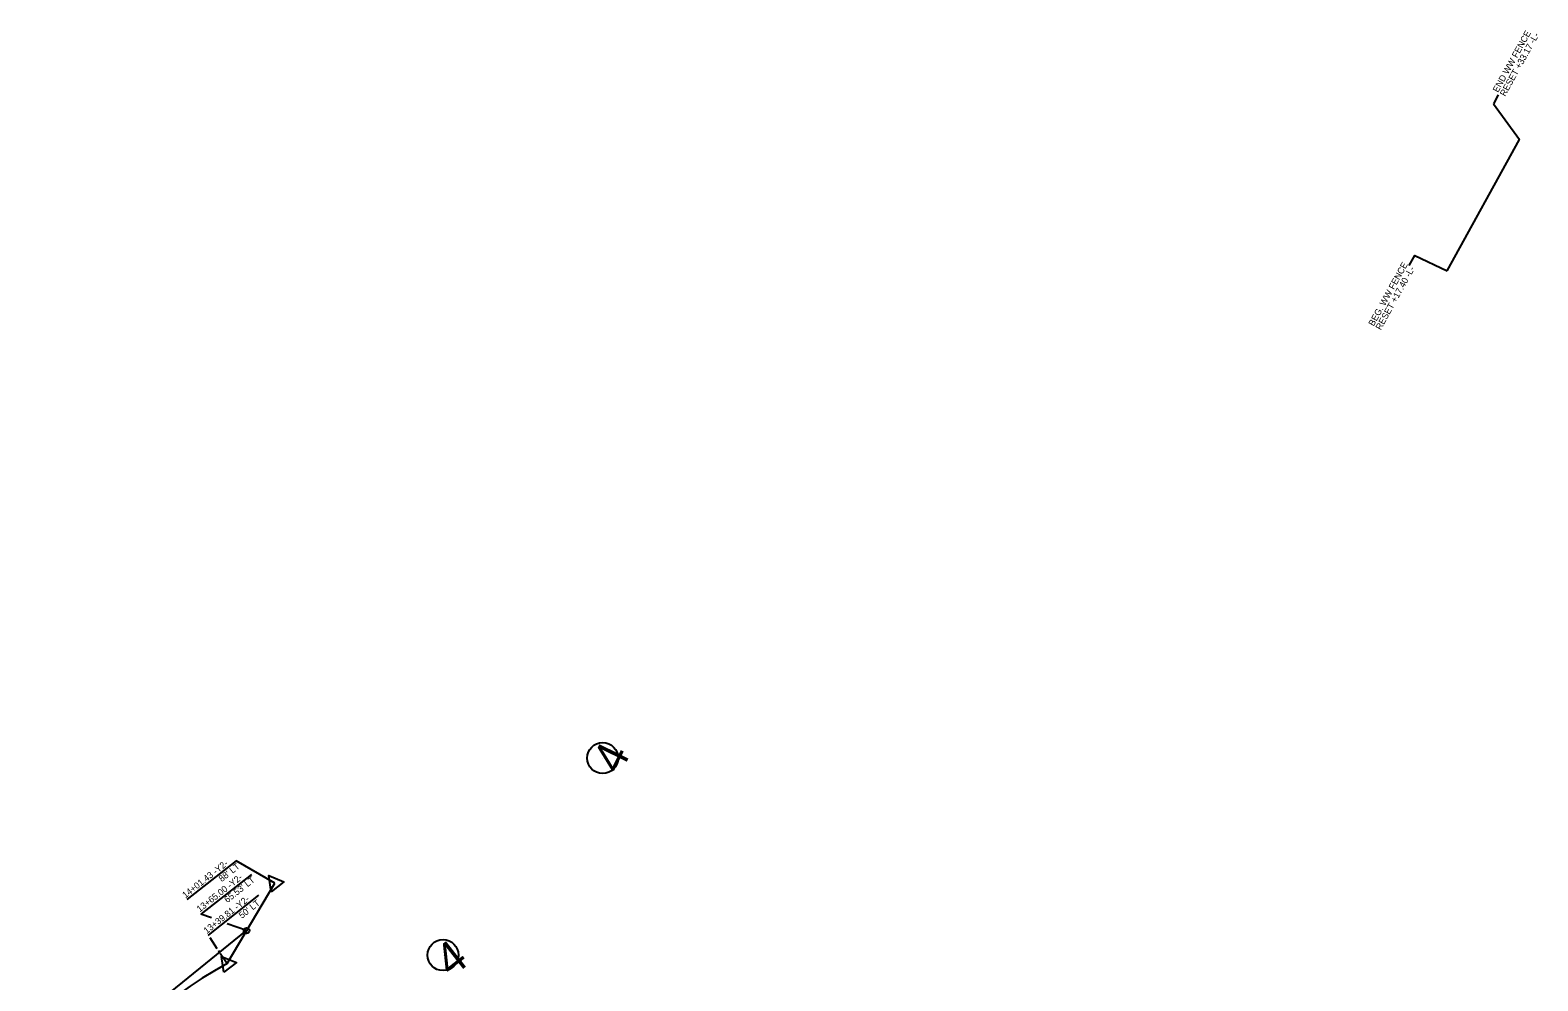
# Model space of a CAD drawing. Extents: x 2175623 to 2194100, y 76458 to 87202.
# Drawn here: x 2175913 to 2177079, y 77699 to 78434 of the extents above; entities that cross this region are included whole.
import ezdxf

# ---------------------------------------------------------------- set-up
doc = ezdxf.new("R2010")
doc.units = 0
for name, color, linetype in [('Exist Plan Preparation Drainage Flow Arrows', 7, 'Continuous'), ('Exist Property Iron Pin CELL', 7, 'Continuous'), ('Prop Drainage Structure Box Number Symbol CELL', 7, 'Continuous'), ('Prop Drainage Structure Pipe RCP 36in Class IV', 7, 'Continuous'), ('Prop Drainage Structure Pipe Removal Label', 7, 'Continuous'), ('Prop Erosion Rip Rap Pad at Outlet Label', 7, 'Continuous'), ('Prop Plan Preparation Crest Label', 7, 'Continuous'), ('Prop Plan Preparation Sag', 7, 'Continuous'), ('Prop Plan Preparation Sag Label', 7, 'Continuous'), ('Scratch_Level_3', 7, 'Continuous')]:
    doc.layers.add(name, color=color, linetype=linetype)

msp = doc.modelspace()

# ---------------------------------------------------------------- linework, layer by layer
at = {"layer": 'Exist Plan Preparation Drainage Flow Arrows'}
msp.add_line((2176065.7, 77712.6), (2176102.5, 77774.9), dxfattribs=at)
msp.add_arc((2176198.4, 77460.4), 285, 117.7626, 187.9763, dxfattribs=at)
at = {"layer": 'Exist Property Iron Pin CELL'}
for radius in [2.2, 0.0707]:
    msp.add_circle((2176080.7, 77738.1), radius, dxfattribs=at)
at = {"layer": 'Prop Drainage Structure Box Number Symbol CELL'}
for p, q in [((2176355.9, 77871.5), (2176355.9, 77871.5)), ((2176232.5, 77719.2), (2176232.5, 77719.2))]:
    msp.add_line(p, q, dxfattribs=at)
for centre in [(2176355.9, 77871.5), (2176232.5, 77719.2)]:
    msp.add_circle(centre, 12, dxfattribs=at)
at = {"layer": 'Prop Drainage Structure Pipe RCP 36in Class IV'}
for p, q in [((2176084.4, 77781.6), (2176045.3, 77750.8)), ((2176053.5, 77747.9), (2176045.3, 77750.8)), ((2176080.7, 77738.1), (2176065.7, 77743.5))]:
    msp.add_line(p, q, dxfattribs=at)
at = {"layer": 'Prop Drainage Structure Pipe Removal Label'}
msp.add_line((2177048.1, 78384), (2177044.3, 78377.1), dxfattribs=at)
for points in [[(2177044.3, 78377.1), (2177064.4, 78349.4)], [(2176979.3, 78252.2), (2176983.5, 78259.9), (2177008.5, 78248)]]:
    msp.add_lwpolyline(points, dxfattribs=at)
at = {"layer": 'Prop Plan Preparation Crest Label'}
for p, q in [((2176102.5, 77774.9), (2176102.5, 77774.9)), ((2176065.7, 77712.6), (2176065.7, 77712.6))]:
    msp.add_line(p, q, dxfattribs=at)
for points in [[(2176099.8, 77768.2), (2176098, 77780.6), (2176109.6, 77775.9)], [(2176063, 77705.9), (2176061.2, 77718.2), (2176072.8, 77713.6)]]:
    msp.add_lwpolyline(points, close=True, dxfattribs=at)
at = {"layer": 'Prop Plan Preparation Sag'}
for p, q in [((2176072.7, 77792.1), (2176034.4, 77762.1)), ((2176102.5, 77774.9), (2176072.7, 77792.1)), ((2176090, 77765.4), (2176050.9, 77734.7)), ((2176050.9, 77734.7), (2176051.2, 77734.3)), ((2176052.2, 77732.8), (2176057.8, 77724.4)), ((2176058.9, 77722.7), (2176059.6, 77721.6)), ((2176060.2, 77720.7), (2176065.7, 77712.6))]:
    msp.add_line(p, q, dxfattribs=at)
at = {"layer": 'Prop Plan Preparation Sag Label'}
msp.add_line((2176022, 77690.6), (2176080.7, 77738.1), dxfattribs=at)
at = {"layer": 'Scratch_Level_3'}
msp.add_line((2177008.5, 78248), (2177064.4, 78349.4), dxfattribs=at)

# ---------------------------------------------------------------- texts
at = {"layer": 'Prop Drainage Structure Pipe RCP 36in Class IV'}
for s, p in [('13+65.00 -Y2- ', (2176044.5, 77752.1)), ("65.53' LT", (2176065.8, 77759.3))]:
    msp.add_text(s, height=5, rotation=38.0951, dxfattribs=at).set_placement(p)
at = {"layer": 'Prop Drainage Structure Pipe Removal Label'}
for s, p in [('END WW FENCE', (2177047.9, 78385.4)), ('RESET +33.17 -L-', (2177053.4, 78382.4)), ('BEG. WW FENCE', (2176951.8, 78204.8)), ('RESET +17.40 -L-', (2176957.3, 78201.8))]:
    msp.add_text(s, height=5, rotation=61.0733, dxfattribs=at).set_placement(p)
at = {"layer": 'Prop Erosion Rip Rap Pad at Outlet Label'}
for rotation, p in [(63.5673, (2176369.4, 77858.2)), (38.0951, (2176238.9, 77701.4))]:
    msp.add_text('4', height=25, rotation=rotation, dxfattribs=at).set_placement(p)
at = {"layer": 'Prop Plan Preparation Sag'}
for s, p in [('14+01.43 -Y2- ', (2176033.4, 77762.9)), ("88' LT", (2176061.5, 77775.5)), ('13+39.81 -Y2- ', (2176049.9, 77735.4)), ("50' LT", (2176077.1, 77747.2))]:
    msp.add_text(s, height=5, rotation=38.0951, dxfattribs=at).set_placement(p)

doc.saveas('drawing.dxf')
